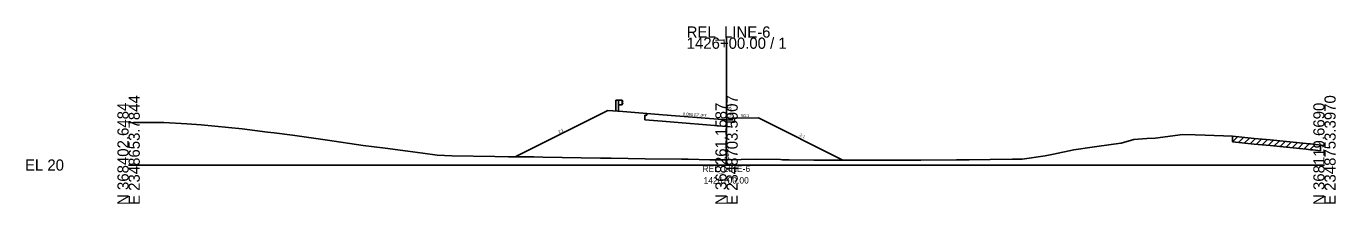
# Model space of a CAD drawing. Extents: x -26 to 403, y -10 to 6565.
# Drawn here: x -25.7 to 302.8, y 5490.3 to 5534.8 of the extents above; entities that cross this region are included whole.
import ezdxf

# ---------------------------------------------------------------- set-up
doc = ezdxf.new("R2010")
doc.units = 0
for name, color, linetype in [('RD_GPK_XS_Cell', 7, 'Continuous'), ('RD_XS_Base', 7, 'Continuous'), ('RD_XS_CurbBase', 7, 'Continuous'), ('RD_XS_CurbFront', 7, 'Continuous'), ('RD_XS_CurbTop', 7, 'Continuous'), ('RD_XS_EarthShd', 7, 'Continuous'), ('RD_XS_ExGround', 7, 'Continuous'), ('RD_XS_ExPaveRet', 7, 'Continuous'), ('RD_XS_GR', 7, 'Continuous'), ('RD_XS_Pave', 7, 'Continuous'), ('RD_XS_PaveShd', 7, 'Continuous'), ('RD_XS_TieSlope', 7, 'Continuous'), ('RD_XS_TX_Elev_EX', 7, 'Continuous'), ('RD_XS_TX_Elev_PR', 7, 'Continuous'), ('RD_XS_TX_Slope', 7, 'Continuous'), ('RD_XS_TX_Station', 7, 'Continuous'), ('RD_XS_TX_TOC', 7, 'Continuous')]:
    doc.layers.add(name, color=color, linetype=linetype)

msp = doc.modelspace()

# ---------------------------------------------------------------- linework, layer by layer
at = {"layer": 'RD_GPK_XS_Cell'}
for p, q in [((150, 5500), (150, 5531.91)), ((0, 5500), (150, 5500)), ((150, 5500), (300, 5500))]:
    msp.add_line(p, q, dxfattribs=at)
at = {"layer": 'RD_XS_Base'}
for p, q in [((129.99, 5512.91), (129.99, 5512.46)), ((129.99, 5512.46), (129.49, 5512.5)), ((129.49, 5512.5), (129.49, 5511.31)), ((133.86, 5510.96), (129.49, 5511.31)), ((133.86, 5510.96), (149.99, 5509.67))]:
    msp.add_line(p, q, dxfattribs=at)
at = {"layer": 'RD_XS_CurbBase'}
for p, q in [((151.49, 5510.71), (149.99, 5510.79)), ((149.99, 5509.67), (149.99, 5510.79)), ((151.99, 5510.71), (151.49, 5510.71)), ((151.99, 5511.71), (151.99, 5510.71))]:
    msp.add_line(p, q, dxfattribs=at)
at = {"layer": 'RD_XS_CurbFront'}
msp.add_line((149.99, 5510.79), (149.99, 5511.29), dxfattribs=at)
at = {"layer": 'RD_XS_CurbTop'}
for p, q in [((149.99, 5511.31), (149.99, 5511.29)), ((149.99, 5511.29), (151.41, 5511.21)), ((151.41, 5511.21), (151.49, 5511.71)), ((151.49, 5511.71), (151.99, 5511.71))]:
    msp.add_line(p, q, dxfattribs=at)
at = {"layer": 'RD_XS_EarthShd'}
for p, q in [((120.24, 5513.69), (96.99, 5502.06)), ((123.99, 5513.39), (120.24, 5513.69)), ((129.99, 5512.91), (123.99, 5513.39)), ((151.99, 5511.71), (157.99, 5511.83))]:
    msp.add_line(p, q, dxfattribs=at)
at = {"layer": 'RD_XS_ExGround'}
msp.add_lwpolyline([(0, 5510.6), (1.25, 5510.61), (8.84, 5510.64), (14.6, 5510.34), (18.22, 5510.1), (28.49, 5509.1), (34.83, 5508.24), (36.52, 5508.06), (41.08, 5507.5), (49.9, 5506.2), (58.84, 5504.91), (64.36, 5504.2), (70.02, 5503.5), (73.78, 5502.96), (77.43, 5502.51), (81.12, 5502.33), (91.89, 5502.11), (95.26, 5502.07), (101.68, 5502.05), (103.89, 5501.97), (118.38, 5501.71), (119.24, 5501.7), (120.07, 5501.7), (121.04, 5501.68), (129.57, 5501.54), (138.68, 5501.51), (140.35, 5501.51), (145.83, 5501.33), (148.03, 5501.27), (148.42, 5501.27), (150, 5501.31), (157.32, 5501.51), (163.54, 5501.36), (164.05, 5501.33), (165.74, 5501.32), (171.91, 5501.26), (173.18, 5501.26), (178.66, 5501.25), (188.93, 5501.19), (194.49, 5501.21), (195.2, 5501.21), (198.75, 5501.24), (207.69, 5501.31), (210.89, 5501.34), (216.09, 5501.41), (221.74, 5501.44), (224.16, 5501.46), (229.93, 5502.32), (232.03, 5502.76), (237.1, 5503.79), (241.72, 5504.47), (247.09, 5505.24), (249.03, 5505.48), (252.17, 5506.43), (255.42, 5506.65), (257.5, 5506.73), (264.49, 5507.66), (267.54, 5507.58), (270.03, 5507.45), (276.89, 5507.24), (282.35, 5506.64), (286.36, 5506.33), (295.4, 5505.41), (296.03, 5505.33), (296.52, 5505.28), (297.08, 5505.23), (300, 5504.91)], dxfattribs=at)
at = {"layer": 'RD_XS_ExPaveRet'}
for p, q in [((276.89, 5505.8), (276.89, 5507.24)), ((276.89, 5505.8), (278.18, 5507.1)), ((278.39, 5505.64), (279.68, 5506.93)), ((279.89, 5505.48), (281.18, 5506.77)), ((281.39, 5505.31), (282.69, 5506.62)), ((282.89, 5505.17), (284.22, 5506.5)), ((284.39, 5505.05), (285.72, 5506.38)), ((285.89, 5504.93), (287.2, 5506.25)), ((276.89, 5505.8), (282.35, 5505.21)), ((282.35, 5505.21), (286.36, 5504.89)), ((286.36, 5504.89), (295.4, 5503.98)), ((287.39, 5504.79), (288.69, 5506.09)), ((288.89, 5504.64), (290.19, 5505.94)), ((290.39, 5504.49), (291.69, 5505.79)), ((291.89, 5504.33), (293.19, 5505.64)), ((293.39, 5504.18), (294.69, 5505.49)), ((294.89, 5504.03), (296.17, 5505.32)), ((295.4, 5503.98), (296.03, 5503.9)), ((296.03, 5503.9), (296.52, 5503.84)), ((296.39, 5503.85), (297.69, 5505.16)), ((296.52, 5503.84), (297.08, 5503.79)), ((297.08, 5503.79), (299, 5503.58)), ((299, 5505.02), (299, 5503.58))]:
    msp.add_line(p, q, dxfattribs=at)
at = {"layer": 'RD_XS_GR'}
for p, q in [((122.91, 5516.22), (122.24, 5516.22)), ((122.24, 5516.22), (122.24, 5513.53)), ((123.83, 5516.22), (122.91, 5516.22)), ((122.91, 5516.22), (122.91, 5513.48)), ((123.83, 5515.05), (123.83, 5516.22)), ((123.83, 5516.15), (123.99, 5515.95)), ((123.83, 5515.05), (122.91, 5515.05)), ((123.99, 5515.9), (123.83, 5515.7)), ((123.99, 5515.38), (123.83, 5515.58)), ((123.83, 5515.13), (123.99, 5515.33)), ((123.99, 5515.95), (123.99, 5515.9)), ((123.99, 5515.33), (123.99, 5515.38))]:
    msp.add_line(p, q, dxfattribs=at)
at = {"layer": 'RD_XS_Pave'}
msp.add_line((133.99, 5512.59), (149.99, 5511.31), dxfattribs=at)
at = {"layer": 'RD_XS_PaveShd'}
msp.add_line((133.99, 5512.59), (129.99, 5512.91), dxfattribs=at)
at = {"layer": 'RD_XS_TieSlope'}
msp.add_line((157.99, 5511.83), (179.15, 5501.25), dxfattribs=at)

# ---------------------------------------------------------------- texts
at = {"layer": 'RD_GPK_XS_Cell'}
for s, p in [('REL_LINE-6', (140, 5531.91)), ('1426+00.00 / 1', (140, 5529.11)), ('EL 20', (-26, 5498.6))]:
    msp.add_text(s, height=2.8, dxfattribs=at).set_placement(p)
for s, p in [('E 2348653.7844', (2.8, 5490)), ('E 2348703.5907', (152.8, 5490)), ('E 2348753.3970', (302.8, 5490)), ('N 368402.6484', (0, 5490)), ('N 368261.1587', (150, 5490)), ('N 368119.6690', (300, 5490))]:
    msp.add_text(s, height=2.8, rotation=90, dxfattribs=at).set_placement(p)
at = {"layer": 'RD_XS_TX_Elev_EX'}
msp.add_text('21.31', height=1, rotation=90, dxfattribs=at).set_placement((150.5, 5501.31))
at = {"layer": 'RD_XS_TX_Elev_PR'}
msp.add_text('31.31', height=1.2, rotation=90, dxfattribs=at).set_placement((151.2, 5511.31))
at = {"layer": 'RD_XS_TX_Slope'}
for s, rotation, p in [('0.080 FT./FT.', 355.4261, (138.99, 5512.44)), ('50:1', 1.1458, (153.67, 5512)), ('2:1', 26.5651, (107.92, 5507.88)), ('2:1', 333.4349, (168.21, 5507.28))]:
    msp.add_text(s, height=0.75, rotation=rotation, dxfattribs=at).set_placement(p)
at = {"layer": 'RD_XS_TX_Station'}
for s, p in [('REL_LINE-6', (143.92, 5498.27)), ('1426+00.00', (144.23, 5495.37))]:
    msp.add_text(s, height=1.6, dxfattribs=at).set_placement(p)
at = {"layer": 'RD_XS_TX_TOC'}
msp.add_text('TOCRT', height=0.05, dxfattribs=at).set_placement((151.21, 5511.66))

doc.saveas('drawing.dxf')
